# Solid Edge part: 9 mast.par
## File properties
Author: Henri
Template: Normal.par
Last saved by: Henri
Revision: 8
Application: Solid Edge
Accuracy: 0,990
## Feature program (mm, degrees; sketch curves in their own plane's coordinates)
sketch for "unnamed Protrusion 1" plane through (0, 0, 0) normal (0, 0, 1) x-axis (1, 0, 0)
  line (9.5, -7.5) -> (-9.5, -7.5)
  arc centre (-9.5, -4.5) radius 3 from (-12.5, -4.5) to (-9.5, -7.5) ccw
  line (-12.5, -4.5) -> (-12.5, 4.5)
  arc centre (-9.5, 4.5) radius 3 from (-12.5, 4.5) to (-9.5, 7.5) cw
  line (-9.5, 7.5) -> (9.5, 7.5)
  arc centre (9.5, 4.5) radius 3 from (9.5, 7.5) to (12.5, 4.5) cw
  line (12.5, 4.5) -> (12.5, -4.5)
  arc centre (9.5, -4.5) radius 3 from (9.5, -7.5) to (12.5, -4.5) ccw
extrude "unnamed Protrusion 1" add finite 1000 along +normal
sketch used by "ExtrudedProtrusion_2" plane through (0, 0, 0) normal (1, 0, 0) x-axis (0, 1, 0)
extrude "ExtrudedProtrusion_2" add finite 400 along -normal
sketch for "ExtrudedCutout_1" plane through (0, 0, 990) normal (0, 0, 1) x-axis (0, 1, 0)
  line (-3.75, 8.5) -> (3.75, 8.5)
  line (3.75, 10) -> (3.75, 8.5)
  line (1.5, 10) -> (3.75, 10)
  line (1.5, 10) -> (1.5, 12.5)
  line (-1.5, 12.5) -> (1.5, 12.5)
  line (-1.5, 10) -> (-1.5, 12.5)
  line (-3.75, 10) -> (-1.5, 10)
  line (-3.75, 8.5) -> (-3.75, 10)
extrude "ExtrudedCutout_1" cut finite 625 along -normal
sketch for "ExtrudedProtrusion_3" plane through (0, 0, 350) normal (0, 0, 1) x-axis (1, 0, 0)
  circle centre (-395, 0) radius 2.5
extrude "ExtrudedProtrusion_3" add finite 5 along +normal
sketch for "ExtrudedProtrusion_5" plane through (0, 0, 988.5) normal (0, 0, 1) x-axis (0, 1, 0)
  line (-1.25, 17.25) -> (-1.25, 9.75)
  line (-1.25, 9.75) -> (-3.5, 9.75)
  line (-3.5, 9.75) -> (-3.5, 8.75)
  line (-3.5, 8.75) -> (3.5, 8.75)
  line (3.5, 8.75) -> (3.5, 9.75)
  line (3.5, 9.75) -> (1.25, 9.75)
  line (1.25, 9.75) -> (1.25, 17.25)
  line (-1.25, 17.25) -> (1.25, 17.25)
extrude "ExtrudedProtrusion_5" add finite 5 along -normal
fillet "Round_2" radius 0.25
sketch for "unnamed Cutout 1" plane through (-13.5, -1.25, 986) normal (0, -1, 0) x-axis (1, 0, 0)
  circle centre (-1.75, 0) radius 1.25
extrude "unnamed Cutout 1" cut through along -normal
fillet "Round_4" radius 0.25
sketch for "ExtrudedProtrusion_8" #1 plane through (-395, 0, 350) normal (-1, 0, 0) x-axis (0, -1, 0)
  arc centre (0, 8) radius 2 from (1.2494, 6.4383) to (0, 10) ccw
  line (1.2494, 6.4383) -> (1.2494, 5)
  line (-1.2494, 5) -> (1.2494, 5)
  line (-1.2494, 6.4383) -> (-1.2494, 5)
sketch for "ExtrudedProtrusion_8" #2 plane through (-395, 0, 350) normal (-1, 0, 0) x-axis (0, -1, 0)
  arc centre (0, 8) radius 1.5 from (0, 6.5) to (0, 9.5) ccw
extrude "ExtrudedProtrusion_8" add finite 2.5 symmetric
fillet "Round_7" radius 0.15
sketch for "ExtrudedProtrusion_9" plane through (0, 0, 350) normal (0, 0, 1) x-axis (1, 0, 0)
  circle centre (-22.5, 0) radius 2.5
extrude "ExtrudedProtrusion_9" add finite 5 along +normal
sketch for "ExtrudedProtrusion_10" #1 plane through (-22.5, 0, 0) normal (1, 0, 0) x-axis (0, 1, 0)
  line (1.2494, 355) -> (-1.2494, 355)
  line (-1.2494, 355) -> (-1.2494, 356.4383)
  arc centre (0, 358) radius 2 from (-1.2494, 356.4383) to (1.2494, 356.4383) cw
  line (1.2494, 356.4383) -> (1.2494, 355)
sketch for "ExtrudedProtrusion_10" #2 plane through (-22.5, 0, 0) normal (1, 0, 0) x-axis (0, 1, 0)
  circle centre (0, 358) radius 1.5
extrude "ExtrudedProtrusion_10" add finite 2.5 symmetric
fillet "Round_8" radius 0.15
sketch for "ExtrudedProtrusion_11" plane through (-400, 0, 350) normal (-1, 0, 0) x-axis (0, -1, 0)
  circle centre (0, 8) radius 1.4
extrude "ExtrudedProtrusion_11" add finite 385 along -normal
sketch for "ExtrudedProtrusion_12" #1 plane through (-393.5, 0, 350) normal (-1, 0, 0) x-axis (0, -1, 0)
  circle centre (0, 8) radius 1.45
sketch for "ExtrudedProtrusion_12" #2 plane through (-393.5, 0, 350) normal (-1, 0, 0) x-axis (0, -1, 0)
  line (0.1, 636) -> (0.1, 9.4967)
  line (-0.1, 636) -> (-0.1, 9.4967)
  line (-0.1, 636) -> (0.1, 636)
extrude "ExtrudedProtrusion_12" add finite 369 along -normal
sketch for "ExtrudedCutout_8" plane through (-209, -0.1, 672.7483) normal (0, -1, 0) x-axis (1, 0, 0)
  line (-184.5, -310.2267) -> (184.5, 303.8925)
  line (184.5, 303.8925) -> (184.5, 313.2517)
  line (184.5, 313.2517) -> (-184.5, 313.2517)
  line (-184.5, -310.2267) -> (-184.5, 313.2517)
extrude "ExtrudedCutout_8" cut finite 1 symmetric
swept protrusion "unnamed SweptProtrusion 1"
swept cutout "unnamed SweptCutout 1"
swept protrusion "unnamed SweptProtrusion 2"
sketch for "ExtrudedProtrusion_15" #1 plane through (-13, 0, 986) normal (0, 0, 1) x-axis (1, 0, 0)
  circle centre (-4.2292, 0) radius 1.4
sketch for "ExtrudedProtrusion_15" #2 plane through (-13, 0, 986) normal (0, 0, 1) x-axis (1, 0, 0)
  circle centre (-4.2292, 0) radius 1.875
extrude "ExtrudedProtrusion_15" add finite 0.5 symmetric
fillet "Round_9" radius 2.5
fillet "Round_10" radius 2.5
sketch used by "ExtrudedCutout_9" plane through (0, 0, 0) normal (0, 0, 1) x-axis (1, 0, 0)
extrude "ExtrudedCutout_9" cut finite 75 along +normal
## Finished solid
Body 1: solid body, 156 faces, 314 edges, 166 vertices, 4 separate solids.
  Faces by surface: cylinder 67, plane 48, torus 31, sphere 10
  Edges by curve: circle 157, line 139, intersection 12, ellipse 6
Bounding box of the edges (mm; curved faces can reach further): 412.500 x 15.000 x 925.000, from (-400, -7.5, 75) to (12.5, 7.5, 1000).
Cylindrical faces by radius (mm): R0.15 x18, R0.25 x24, R0.27 x1, R0.28 x1, R1.25 x1, R1.4 x2, R1.45 x1, R1.5 x3, R1.875 x1, R2 x2, R2.5 x8, R3 x4, R5 x1
Toroidal faces (ring radius, tube radius in mm): R0.3 r0.15 x12, R0.5 r0.25 x4, R0.5 r2.5 x4, R1.5 r0.25 x2, R1.65 r0.15 x4, R1.85 r0.15 x4, R2.5 r2.5 x1
Spherical faces by radius (mm): R0.25 x10
Planar faces by outward normal: +x 8, +y 8, +z 6, -x 11, -y 8, -z 4, oblique 3
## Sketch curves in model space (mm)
circle centre (-17.2292, 0, 986) radius 1.4
circle centre (-17.2292, 0, 986) radius 1.875
line (-395.0152, 0, 360) -> (-18.8764, 0, 986)
line (-24.5, -0.1, 976.6408) -> (-24.5, -0.1, 986)
line (-24.5, -0.1, 986) -> (-393.5, -0.1, 986)
line (-393.5, -0.1, 362.5217) -> (-393.5, -0.1, 986)
line (-393.5, -0.1, 362.5217) -> (-24.5, -0.1, 976.6408)
circle centre (-24.5, 0, 976.6408) radius 0.25
circle centre (-24.5, 0, 976.6408) radius 0.27
circle centre (-24.5, 0, 976.6408) radius 0.28
line (-393.7718, 0, 362.0693) -> (-24.5, 0, 976.6408)
line (15.8183, 11.3131, 0) -> (15.8183, -9.7112, 0)
line (15.8183, -9.7112, 0) -> (-16.0185, -9.7112, 0)
line (-16.0185, -9.7112, 0) -> (-16.0185, 11.3131, 0)
line (-16.0185, 11.3131, 0) -> (15.8183, 11.3131, 0)
circle centre (-393.5, 0, 358) radius 1.45
arc centre (-393.5, 0, 358) radius 1.5 from (-393.5, -0.1, 359.4967) through (-393.5, 0.2231, 356.5167) to (-393.5, 0.1, 359.4967)
line (-393.5, -0.1, 986) -> (-393.5, -0.1, 359.4967)
line (-393.5, 0.1, 986) -> (-393.5, -0.1, 986)
line (-393.5, 0.1, 986) -> (-393.5, 0.1, 359.4967)
circle centre (-400, 0, 358) radius 1.4
circle centre (-22.5, 0, 358) radius 1.5
arc centre (-22.5, 0, 358) radius 2 from (-22.5, -1.2494, 356.4383) through (-22.5, 0.1188, 359.9965) to (-22.5, 1.2494, 356.4383)
line (-22.5, 1.2494, 356.4383) -> (-22.5, 1.2494, 355)
line (-22.5, 1.2494, 355) -> (-22.5, -1.2494, 355)
line (-22.5, -1.2494, 355) -> (-22.5, -1.2494, 356.4383)
circle centre (-22.5, 0, 350) radius 2.5
line (-20.4618, 0, 350) -> (-29.1715, 0, 350)
line (-22.5, 11.3125, 350) -> (-22.5, -3.7004, 350)
line (-395, -1.2494, 356.4383) -> (-395, -1.2494, 355)
arc centre (-395, 0, 358) radius 2 from (-395, -1.2494, 356.4383) through (-395, -1.8873, 358.662) to (-395, 0, 360)
arc centre (-395, 0, 358) radius 2 from (-395, 1.2494, 356.4383) through (-395, 1.8873, 358.662) to (-395, 0, 360)
line (-395, 1.2494, 356.4383) -> (-395, 1.2494, 355)
line (-395, 1.2494, 355) -> (-395, -1.2494, 355)
arc centre (-395, 0, 358) radius 1.5 from (-395, 0, 356.5) through (-395, -1.4993, 358.0444) to (-395, 0, 359.5)
arc centre (-395, 0, 358) radius 1.5 from (-395, 0, 356.5) through (-395, 1.4993, 358.0444) to (-395, 0, 359.5)
line (-19.5, 0, 995.3814) -> (-19.5, 0, 365)
line (-397.3443, 0, 365) -> (-19.5, 0, 365)
circle centre (-15.25, -1.25, 986) radius 1.25
line (-15.25, -1.25, 989.393) -> (-15.25, -1.25, 989.9351)
line (-17.8885, -1.25, 986) -> (-12.9371, -1.25, 986)
line (-9.75, -1.25, 988.5) -> (-9.75, -3.5, 988.5)
line (-9.75, -3.5, 988.5) -> (-8.75, -3.5, 988.5)
line (-8.75, -3.5, 988.5) -> (-8.75, 3.5, 988.5)
line (-8.75, 3.5, 988.5) -> (-9.75, 3.5, 988.5)
line (-9.75, 3.5, 988.5) -> (-9.75, 1.25, 988.5)
line (-9.75, 1.25, 988.5) -> (-17.25, 1.25, 988.5)
line (-17.25, -1.25, 988.5) -> (-17.25, 1.25, 988.5)
line (-17.25, -1.25, 988.5) -> (-9.75, -1.25, 988.5)
circle centre (-395, 0, 350) radius 2.5
line (-401.3615, 0, 350) -> (-392.2534, 0, 350)
line (-395, 6.6553, 350) -> (-395, -7.3183, 350)
line (-10, -1.5, 990) -> (-12.5, -1.5, 990)
line (-12.5, -1.5, 990) -> (-12.5, 1.5, 990)
line (-10, 1.5, 990) -> (-12.5, 1.5, 990)
line (-10, 1.5, 990) -> (-10, 3.75, 990)
line (-10, 3.75, 990) -> (-8.5, 3.75, 990)
line (-8.5, -3.75, 990) -> (-8.5, 3.75, 990)
line (-8.5, -3.75, 990) -> (-10, -3.75, 990)
line (-10, -3.75, 990) -> (-10, -1.5, 990)
circle centre (0, 0, 350) radius 5
line (0, -59.7176, 350) -> (0, 77.3615, 350)
line (0, 0, 357.4172) -> (0, 0, 344.5068)
arc centre (9.5, 4.5, 0) radius 3 from (9.5, 7.5, 0) through (11.6821, 6.5587, 0) to (12.5, 4.5, 0)
line (12.5, 4.5, 0) -> (12.5, -4.5, 0)
arc centre (9.5, -4.5, 0) radius 3 from (9.5, -7.5, 0) through (11.6821, -6.5587, 0) to (12.5, -4.5, 0)
line (9.5, -7.5, 0) -> (-9.5, -7.5, 0)
arc centre (-9.5, -4.5, 0) radius 3 from (-12.5, -4.5, 0) through (-11.5587, -6.6821, 0) to (-9.5, -7.5, 0)
line (-12.5, -4.5, 0) -> (-12.5, 4.5, 0)
arc centre (-9.5, 4.5, 0) radius 3 from (-12.5, 4.5, 0) through (-11.5587, 6.6821, 0) to (-9.5, 7.5, 0)
line (-9.5, 7.5, 0) -> (9.5, 7.5, 0)
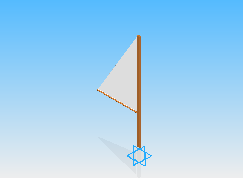
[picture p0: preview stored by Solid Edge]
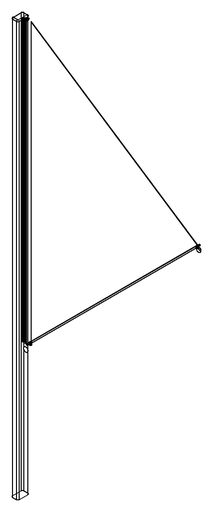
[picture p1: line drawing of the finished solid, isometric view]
